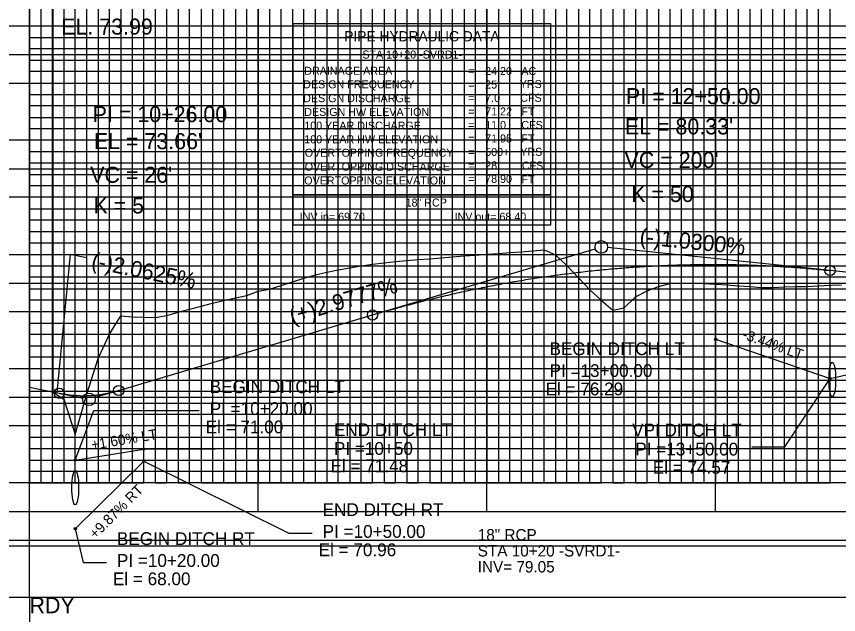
# Model space of a CAD drawing. Extents: x 2345490 to 2436403, y 465165 to 573888.
# Drawn here: x 2381761.1 to 2382120.5, y 510396.8 to 510658.5 of the extents above; entities that cross this region are included whole.
import ezdxf

# ---------------------------------------------------------------- set-up
doc = ezdxf.new("R2010")
doc.units = 0
for name, color, linetype in [('Old_Level_1', 7, 'Continuous'), ('Old_Level_18', 7, 'Continuous'), ('Old_Level_2', 7, 'Continuous'), ('Old_Level_3', 7, 'Continuous'), ('Old_Level_4', 7, 'Continuous'), ('Old_Level_41', 7, 'Continuous'), ('Old_Level_42', 7, 'Continuous'), ('Old_Level_43', 7, 'Continuous'), ('Old_Level_50', 7, 'Continuous'), ('Old_Level_51', 7, 'Continuous'), ('Old_Level_57', 7, 'Continuous'), ('Old_Level_63', 7, 'Continuous'), ('Prop Vertical Profile Grade', 7, 'Continuous')]:
    doc.layers.add(name, color=color, linetype=linetype)

msp = doc.modelspace()

# ---------------------------------------------------------------- linework, layer by layer
at = {"layer": 'Old_Level_1'}
msp.add_lwpolyline([(2381766.799, 510496.38628), (2381771.799, 510495.26652), (2381776.799, 510494.29703), (2381781.799, 510491.09236), (2381786.799, 510475.545), (2381791.799, 510493.23682), (2381796.799, 510508.82896), (2381801.799, 510519.43585), (2381806.799, 510527.46772), (2381811.799, 510527.16316), (2381816.799, 510526.92701), (2381821.799, 510526.73293), (2381826.799, 510527.68325), (2381831.799, 510529.13877), (2381836.799, 510530.47008), (2381841.799, 510531.75771), (2381846.799, 510533.00023), (2381851.799, 510534.19626), (2381856.799, 510535.34447), (2381861.799, 510536.44358), (2381866.799, 510538.26535), (2381871.799, 510539.18964), (2381876.799, 510540.85295), (2381881.799, 510542.44657), (2381886.799, 510543.96872), (2381891.799, 510545.41772), (2381896.799, 510546.68661), (2381901.799, 510547.6733), (2381906.799, 510548.57556), (2381911.799, 510549.39239), (2381916.799, 510550.12286), (2381921.799, 510550.76618), (2381926.799, 510551.32163), (2381931.799, 510551.78859), (2381936.799, 510552.17014), (2381941.799, 510552.5288), (2381946.799, 510552.88746), (2381951.799, 510553.34688), (2381956.799, 510553.71799), (2381961.799, 510554.0891), (2381966.799, 510554.46021), (2381971.799, 510554.83132), (2381976.799, 510555.20243), (2381981.799, 510555.57354), (2381986.799, 510555.94465), (2381991.799, 510556.34881), (2381996.799, 510554.23512), (2382001.799, 510549.54421), (2382006.799, 510544.21219), (2382011.799, 510538.85622), (2382016.799, 510534.42474), (2382021.799, 510529.99327), (2382026.799, 510531.06065), (2382031.799, 510535.83309), (2382036.799, 510538.39836), (2382041.799, 510540.30035), (2382046.799, 510541.74515), (2382051.799, 510541.98873), (2382056.799, 510541.81563), (2382061.799, 510541.64254), (2382066.799, 510541.39711), (2382071.799, 510541.05134), (2382076.799, 510540.72909), (2382081.799, 510540.40571), (2382086.799, 510539.94628), (2382091.799, 510539.9297), (2382096.799, 510540.14654), (2382101.799, 510540.31913), (2382106.799, 510540.43366), (2382111.799, 510540.67643), (2382116.799, 510540.9192), (2382121.799, 510541.16197)], dxfattribs=at)
at = {"layer": 'Old_Level_18'}
msp.add_lwpolyline([(2383216.79875, 511479.3835), (2381716.79875, 511479.3835), (2381716.79875, 510429.3835), (2383216.79875, 510429.3835)], close=True, dxfattribs=at)
at = {"layer": 'Old_Level_2'}
for p, q in [((2381777.109, 510494.2375), (2381777.109, 510684.44001)), ((2382116.799, 510547.3835), (2382116.799, 510681.70631)), ((2381784.50848, 510554.29431), (2381778.8217, 510494.02737)), ((2381791.76888, 510552.84223), (2381784.50848, 510554.29431)), ((2381916.799, 510527.90671), (2382014.16336, 510556.89869)), ((2382116.799, 510547.3835), (2382019.53453, 510557.40174)), ((2381779.799, 510493.66475), (2381790.10569, 510491.539)), ((2381805.799, 510494.85448), (2381795.43464, 510491.76831))]:
    msp.add_line(p, q, dxfattribs=at)
for centre, radius in [((2382016.799, 510557.6835), 2.75), ((2382116.799, 510547.3835), 2.25), ((2381916.799, 510527.90671), 2.25), ((2381805.799, 510494.85448), 2.25), ((2381779.799, 510493.66475), 2.25), ((2381792.799, 510490.9835), 2.75)]:
    msp.add_circle(centre, radius, dxfattribs=at)
at = {"layer": 'Old_Level_3'}
for p, q in [((2382066.799, 510504.39502), (2382066.799, 510517.2835)), ((2382066.799, 510517.2835), (2382116.799, 510500.0835)), ((2382116.799, 510500.0835), (2382166.799, 510511.3835)), ((2382049.36634, 510504.39502), (2382066.799, 510504.39502)), ((2382097.05969, 510470.20539), (2382116.799, 510500.0835)), ((2381786.799, 510464.3835), (2381794.9392, 510486.13954)), ((2381794.9392, 510486.13954), (2381841.03359, 510486.13954)), ((2381786.799, 510464.3835), (2381816.799, 510469.1835)), ((2381816.799, 510469.1835), (2381879.16663, 510469.46159)), ((2381879.16663, 510469.46159), (2381892.35737, 510469.46159)), ((2382082.54842, 510470.20539), (2382097.05969, 510470.20539)), ((2381786.799, 510434.3835), (2381816.799, 510463.9835)), ((2381816.799, 510463.9835), (2381880.13742, 510432.37177)), ((2381786.799, 510434.3835), (2381790.19861, 510419.66303)), ((2381880.13742, 510432.37177), (2381890.40218, 510432.37177)), ((2381790.19861, 510419.66303), (2381800.46337, 510419.66303))]:
    msp.add_line(p, q, dxfattribs=at)
for centre in [(2382066.799, 510517.2835), (2382116.799, 510500.0835), (2381816.799, 510469.1835), (2381786.799, 510464.3835), (2381816.799, 510463.9835), (2381786.799, 510434.3835)]:
    msp.add_circle(centre, 0.5, dxfattribs=at)
for centre in [(2382117.799, 510499.6835), (2381786.799, 510452.3835)]:
    msp.add_ellipse(centre, major_axis=(0, 7.5), ratio=0.195724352, dxfattribs=at)
at = {"layer": 'Old_Level_4'}
for p, q in [((2381882.02849, 510655.45163), (2381994.52849, 510655.45163)), ((2381882.02849, 510580.45163), (2381882.02849, 510655.45163)), ((2381994.52849, 510655.45163), (2381994.52849, 510580.45163)), ((2381994.52849, 510580.45163), (2381882.02849, 510580.45163))]:
    msp.add_line(p, q, dxfattribs=at)
msp.add_lwpolyline([(2381882.02849, 510580.45163), (2381994.52849, 510580.45163), (2381994.52849, 510567.23663), (2381882.02849, 510567.23663)], close=True, dxfattribs=at)
at = {"layer": 'Old_Level_41'}
msp.add_line((2383216.79875, 510454.3835), (2381716.79875, 510454.3835), dxfattribs=at)
for points in [[(2381766.79875, 511479.3835), (2381766.79875, 510454.3835), (2381816.79875, 510454.3835), (2381816.79875, 511479.3835)], [(2381791.79875, 510454.3835), (2381791.79875, 511479.3835)], [(2381841.79875, 511479.3835), (2381841.79875, 510454.3835), (2381891.79875, 510454.3835), (2381891.79875, 511479.3835)], [(2381866.79875, 511479.3835), (2381866.79875, 510454.3835), (2381916.79875, 510454.3835), (2381916.79875, 511479.3835)], [(2381941.79875, 511479.3835), (2381941.79875, 510454.3835), (2381991.79875, 510454.3835), (2381991.79875, 511479.3835)], [(2381966.79875, 511479.3835), (2381966.79875, 510454.3835), (2382016.79875, 510454.3835), (2382016.79875, 511479.3835)], [(2382041.79875, 511479.3835), (2382041.79875, 510454.3835), (2382091.79875, 510454.3835), (2382091.79875, 511479.3835)], [(2382066.79875, 511479.3835), (2382066.79875, 510454.3835), (2382116.79875, 510454.3835), (2382116.79875, 511479.3835)], [(2383216.79875, 510679.3835), (2381716.79875, 510679.3835), (2381716.79875, 510629.3835), (2383216.79875, 510629.3835)], [(2383216.79875, 510579.3835), (2381716.79875, 510579.3835), (2381716.79875, 510529.3835), (2383216.79875, 510529.3835)], [(2383216.79875, 510504.3835), (2381716.79875, 510504.3835), (2381716.79875, 510554.3835), (2383216.79875, 510554.3835)], [(2383216.79875, 510479.3835), (2381716.79875, 510479.3835)]]:
    msp.add_lwpolyline(points, dxfattribs=at)
at = {"layer": 'Old_Level_42'}
msp.add_lwpolyline([(2383216.79875, 510604.3835), (2381716.79875, 510604.3835), (2381716.79875, 510654.3835), (2383216.79875, 510654.3835)], dxfattribs=at)
at = {"layer": 'Old_Level_43'}
for points in [[(2381771.79875, 511479.3835), (2381771.79875, 510454.3835), (2381776.79875, 510454.3835), (2381776.79875, 511479.3835)], [(2381781.79875, 511479.3835), (2381781.79875, 510454.3835), (2381786.79875, 510454.3835), (2381786.79875, 511479.3835)], [(2381796.79875, 511479.3835), (2381796.79875, 510454.3835), (2381801.79875, 510454.3835), (2381801.79875, 511479.3835)], [(2381806.79875, 511479.3835), (2381806.79875, 510454.3835), (2381811.79875, 510454.3835), (2381811.79875, 511479.3835)], [(2381821.79875, 511479.3835), (2381821.79875, 510454.3835), (2381826.79875, 510454.3835), (2381826.79875, 511479.3835)], [(2381831.79875, 511479.3835), (2381831.79875, 510454.3835), (2381836.79875, 510454.3835), (2381836.79875, 511479.3835)], [(2381846.79875, 511479.3835), (2381846.79875, 510454.3835), (2381851.79875, 510454.3835), (2381851.79875, 511479.3835)], [(2381856.79875, 511479.3835), (2381856.79875, 510454.3835), (2381861.79875, 510454.3835), (2381861.79875, 511479.3835)], [(2381871.79875, 511479.3835), (2381871.79875, 510454.3835), (2381876.79875, 510454.3835), (2381876.79875, 511479.3835)], [(2381881.79875, 511479.3835), (2381881.79875, 510454.3835), (2381886.79875, 510454.3835), (2381886.79875, 511479.3835)], [(2381896.79875, 511479.3835), (2381896.79875, 510454.3835), (2381901.79875, 510454.3835), (2381901.79875, 511479.3835)], [(2381906.79875, 511479.3835), (2381906.79875, 510454.3835), (2381911.79875, 510454.3835), (2381911.79875, 511479.3835)], [(2381921.79875, 511479.3835), (2381921.79875, 510454.3835), (2381926.79875, 510454.3835), (2381926.79875, 511479.3835)], [(2381931.79875, 510454.3835), (2381936.79875, 510454.3835), (2381936.79875, 511479.3835)], [(2381931.79875, 511479.3835), (2381931.79875, 510454.3835)], [(2381946.79875, 511479.3835), (2381946.79875, 510454.3835), (2381951.79875, 510454.3835), (2381951.79875, 511479.3835)], [(2381956.79875, 511479.3835), (2381956.79875, 510454.3835), (2381961.79875, 510454.3835), (2381961.79875, 511479.3835)], [(2381971.79875, 511479.3835), (2381971.79875, 510454.3835), (2381976.79875, 510454.3835), (2381976.79875, 511479.3835)], [(2381981.79875, 511479.3835), (2381981.79875, 510454.3835), (2381986.79875, 510454.3835), (2381986.79875, 511479.3835)], [(2381996.79875, 511479.3835), (2381996.79875, 510454.3835), (2382001.79875, 510454.3835), (2382001.79875, 511479.3835)], [(2382006.79875, 511479.3835), (2382006.79875, 510454.3835), (2382011.79875, 510454.3835), (2382011.79875, 511479.3835)], [(2382021.79875, 511479.3835), (2382021.79875, 510454.3835), (2382026.79875, 510454.3835), (2382026.79875, 511479.3835)], [(2382031.79875, 511479.3835), (2382031.79875, 510454.3835), (2382036.79875, 510454.3835), (2382036.79875, 511479.3835)], [(2382046.79875, 511479.3835), (2382046.79875, 510454.3835), (2382051.79875, 510454.3835), (2382051.79875, 511479.3835)], [(2382056.79875, 511479.3835), (2382056.79875, 510454.3835), (2382061.79875, 510454.3835), (2382061.79875, 511479.3835)], [(2382071.79875, 511479.3835), (2382071.79875, 510454.3835), (2382076.79875, 510454.3835), (2382076.79875, 511479.3835)], [(2382081.79875, 511479.3835), (2382081.79875, 510454.3835), (2382086.79875, 510454.3835), (2382086.79875, 511479.3835)], [(2382096.79875, 511479.3835), (2382096.79875, 510454.3835), (2382111.79875, 510454.3835), (2382111.79875, 511479.3835)], [(2382101.79875, 511479.3835), (2382101.79875, 510454.3835), (2382106.79875, 510454.3835), (2382106.79875, 511479.3835)], [(2382101.79875, 511478.7835), (2382101.79875, 510454.3835), (2382106.79875, 510454.3835), (2382106.79875, 511478.7835)], [(2381766.79875, 510649.3835), (2383166.79875, 510649.3835)], [(2383166.79875, 510644.3835), (2381766.79875, 510644.3835), (2381766.79875, 510639.3835), (2383166.79875, 510639.3835)], [(2383166.79875, 510634.3835), (2381766.79875, 510634.3835)], [(2381766.79875, 510624.3835), (2383166.79875, 510624.3835)], [(2383166.79875, 510619.3835), (2381766.79875, 510619.3835), (2381766.79875, 510614.3835), (2383166.79875, 510614.3835)], [(2383166.79875, 510609.3835), (2381766.79875, 510609.3835), (2381766.79875, 510599.3835), (2383166.79875, 510599.3835)], [(2383166.79875, 510594.3835), (2381766.79875, 510594.3835), (2381766.79875, 510589.3835), (2383166.79875, 510589.3835)], [(2383166.79875, 510584.3835), (2381766.79875, 510584.3835), (2381766.79875, 510574.3835), (2383166.79875, 510574.3835)], [(2383166.79875, 510569.3835), (2381766.79875, 510569.3835), (2381766.79875, 510564.3835), (2383166.79875, 510564.3835)], [(2383166.79875, 510559.3835), (2381766.79875, 510559.3835), (2381766.79875, 510549.3835), (2383166.79875, 510549.3835)], [(2383166.79875, 510544.3835), (2381766.79875, 510544.3835), (2381766.79875, 510539.3835), (2383166.79875, 510539.3835)], [(2383166.79875, 510534.3835), (2381766.79875, 510534.3835), (2381766.79875, 510524.3835), (2383166.79875, 510524.3835)], [(2383166.79875, 510519.3835), (2381766.79875, 510519.3835), (2381766.79875, 510514.3835), (2383166.79875, 510514.3835)], [(2383166.79875, 510509.3835), (2381766.79875, 510509.3835), (2381766.79875, 510499.3835), (2383166.79875, 510499.3835)], [(2383166.79875, 510494.3835), (2381766.79875, 510494.3835), (2381766.79875, 510489.3835), (2383166.79875, 510489.3835)], [(2383166.79875, 510484.3835), (2381766.79875, 510484.3835), (2381766.79875, 510474.3835), (2383166.79875, 510474.3835)], [(2383166.79875, 510469.3835), (2381766.79875, 510469.3835), (2381766.79875, 510464.3835), (2383166.79875, 510464.3835)], [(2383166.79875, 510459.3835), (2381766.79875, 510459.3835)]]:
    msp.add_lwpolyline(points, dxfattribs=at)
at = {"layer": 'Old_Level_50'}
msp.add_lwpolyline([(2383229.29875, 511481.9335), (2381562.79875, 511481.9335), (2381562.79875, 510426.8335), (2383229.29875, 510426.8335)], close=True, dxfattribs=at)
at = {"layer": 'Old_Level_51'}
msp.add_lwpolyline([(2383233.79875, 511504.3835), (2381549.79875, 511504.3835), (2381549.79875, 510404.3835), (2383233.79875, 510404.3835)], close=True, dxfattribs=at)
at = {"layer": 'Old_Level_57'}
for p, q in [((2381766.79875, 510441.88375), (2381766.79875, 510691.88375)), ((2381866.79875, 510441.88375), (2381866.79875, 510691.88375)), ((2381966.79875, 510441.88375), (2381966.79875, 510691.88375)), ((2382066.79875, 510441.88375), (2382066.79875, 510691.88375)), ((2381716.79925, 510641.88375), (2383066.79875, 510641.88375)), ((2381716.79925, 510591.88375), (2383066.79875, 510591.88375)), ((2381716.79925, 510541.88375), (2383066.79875, 510541.88375)), ((2381716.799, 510491.88375), (2383066.79875, 510491.88375)), ((2381716.79925, 510441.88375), (2383066.79875, 510441.88375))]:
    msp.add_line(p, q, dxfattribs=at)
at = {"layer": 'Old_Level_63'}
for q in [(2381766.799, 512904.3835), (2382366.799, 510404.3835), (2381766.799, 507904.3835)]:
    msp.add_line((2381766.799, 510404.3835), q, dxfattribs=at)
at = {"layer": 'Prop Vertical Profile Grade'}
for p, q in [((2382166.799, 510542.02672), (2382116.799, 510547.3835)), ((2381805.799, 510494.85448), (2381916.799, 510527.90671)), ((2381776.799, 510494.2835), (2381779.799, 510493.66475))]:
    msp.add_line(p, q, dxfattribs=at)
for points in [[(2381916.799, 510527.90671), (2381920.799, 510529.08175), (2381924.799, 510530.22473), (2381928.799, 510531.33565), (2381932.799, 510532.41451), (2381936.799, 510533.4613), (2381940.799, 510534.47604), (2381944.799, 510535.45871), (2381948.799, 510536.40932), (2381952.799, 510537.32787), (2381956.799, 510538.21436), (2381960.799, 510539.06878), (2381964.799, 510539.89115), (2381968.799, 510540.68145), (2381972.799, 510541.43969), (2381976.799, 510542.16588), (2381980.799, 510542.85999), (2381984.799, 510543.52205), (2381988.799, 510544.15205), (2381992.799, 510544.74998), (2381996.799, 510545.31586), (2382000.799, 510545.84967), (2382004.799, 510546.35142), (2382008.799, 510546.82111), (2382012.799, 510547.25874), (2382016.799, 510547.6643), (2382020.799, 510548.03781), (2382024.799, 510548.37925), (2382028.799, 510548.68863), (2382032.799, 510548.96596), (2382036.799, 510549.21121), (2382040.799, 510549.42441), (2382044.799, 510549.60555), (2382048.799, 510549.75462), (2382052.799, 510549.87164), (2382056.799, 510549.95659), (2382060.799, 510550.00948), (2382064.799, 510550.03031), (2382068.799, 510550.01908), (2382072.799, 510549.97578), (2382076.799, 510549.90043), (2382080.799, 510549.79301), (2382084.799, 510549.65353), (2382088.799, 510549.482), (2382092.799, 510549.27839), (2382096.799, 510549.04273), (2382100.799, 510548.77501), (2382104.799, 510548.47522), (2382108.799, 510548.14338), (2382112.799, 510547.77947), (2382116.799, 510547.3835)], [(2381779.799, 510493.66475), (2381780.319, 510493.56012), (2381780.839, 510493.46073), (2381781.359, 510493.36659), (2381781.879, 510493.27768), (2381782.399, 510493.19402), (2381782.919, 510493.1156), (2381783.439, 510493.04242), (2381783.959, 510492.97449), (2381784.479, 510492.91179), (2381784.999, 510492.85434), (2381785.519, 510492.80213), (2381786.039, 510492.75516), (2381786.559, 510492.71343), (2381787.079, 510492.67695), (2381787.599, 510492.6457), (2381788.119, 510492.6197), (2381788.639, 510492.59894), (2381789.159, 510492.58342), (2381789.679, 510492.57314), (2381790.199, 510492.56811), (2381790.719, 510492.56831), (2381791.239, 510492.57376), (2381791.759, 510492.58445), (2381792.279, 510492.60038), (2381792.799, 510492.62156), (2381793.319, 510492.64797), (2381793.839, 510492.67963), (2381794.359, 510492.71653), (2381794.879, 510492.75867), (2381795.399, 510492.80605), (2381795.919, 510492.85868), (2381796.439, 510492.91654), (2381796.959, 510492.97965), (2381797.479, 510493.048), (2381797.999, 510493.12159), (2381798.519, 510493.20043), (2381799.039, 510493.2845), (2381799.559, 510493.37382), (2381800.079, 510493.46838), (2381800.599, 510493.56818), (2381801.119, 510493.67322), (2381801.639, 510493.7835), (2381802.159, 510493.89903), (2381802.679, 510494.0198), (2381803.199, 510494.14581), (2381803.719, 510494.27706), (2381804.239, 510494.41355), (2381804.759, 510494.55529), (2381805.279, 510494.70226), (2381805.799, 510494.85448)]]:
    msp.add_spline(points, degree=3, dxfattribs=at)

# ---------------------------------------------------------------- texts
at = {"layer": 'Old_Level_2'}
for s, height, p in [('EL. 73.99', 7.000001, (2381780.66053, 510650.59203)), ('PI = 12+50.00', 7, (2382027.60025, 510620.1666)), ('PI = 10+26.00', 7, (2381794.42908, 510612.27802)), ("EL = 80.33'", 7, (2382027.11891, 510606.90534)), ("EL = 73.66'", 7, (2381794.91042, 510600.46076)), ("VC = 200'", 7, (2382026.98125, 510592.22043)), ("VC = 26'", 7, (2381793.32874, 510585.75548)), ('K = 50', 7, (2382029.86927, 510577.34015)), ('K = 5', 7, (2381794.77276, 510572.31922))]:
    msp.add_text(s, height=height, dxfattribs=at).set_placement(p)
for s, rotation, p in [('(-)1.0300%', 354.1192724, (2382033.32422, 510558.99727)), ('(-)2.0625%', 348.3461594, (2381793.46367, 510548.57707)), ('(+)2.9777%', 16.5818398, (2381881.68354, 510523.93216))]:
    msp.add_text(s, height=7, rotation=rotation, dxfattribs=at).set_placement(p)
at = {"layer": 'Old_Level_3'}
for s, height, rotation, p in [('-3.44% LT', 4.48, 340.1418463, (2382078.11388, 510517.66527)), ('BEGIN DITCH LT', 5.6000004, 360, (2381994.18539, 510510.32954)), ('PI =13+00.00', 5.6000004, 360, (2381994.18539, 510500.76575)), ('BEGIN DITCH LT', 5.6000004, 360, (2381845.59083, 510493.71041)), ('El = 76.29', 5.6, 360, (2381992.42877, 510492.74647)), ('PI =10+20.00', 5.6000004, 360, (2381845.59083, 510484.14662)), ('El = 71.00', 5.6, 360, (2381843.83422, 510476.12734)), ('END DITCH LT', 5.6000004, 360, (2381899.88883, 510474.88935)), ('VPI DITCH LT', 5.6000004, 360, (2382030.29962, 510474.76123)), ('+1.60% LT', 4.48, 9.4623222, (2381794.14851, 510468.85455)), ('PI =10+50', 5.6, 360, (2381899.88883, 510466.69466)), ('PI =13+50.00', 5.6000004, 360, (2382031.66968, 510466.42017)), ('El = 71.48', 5.6, 360, (2381898.42499, 510459.06574)), ('El = 74.57', 5.6, 360, (2382039.30832, 510458.39708)), ('+9.87% RT', 4.48, 44.9999778, (2381795.62558, 510429.66969)), ('END DITCH RT', 5.6000004, 360, (2381894.95942, 510439.94264)), ('PI =10+50.00', 5.6000004, 360, (2381894.95942, 510430.37886)), ('BEGIN DITCH RT', 5.6000004, 360, (2381805.02061, 510427.2339)), ('El = 70.96', 5.6, 360, (2381893.2028, 510422.35957)), ('PI =10+20.00', 5.6000004, 360, (2381805.02061, 510417.67011)), ('El = 68.00', 5.6, 360, (2381803.26399, 510409.65083))]:
    msp.add_text(s, height=height, rotation=rotation, dxfattribs=at).set_placement(p)
for s, height, p in [('18" RCP', 4.999999, (2381962.7762, 510429.22611)), ('STA 10+20 -SVRD1-', 4.9999995, (2381962.7762, 510422.22611)), ('INV= 79.05', 4.999999, (2381962.7762, 510415.22611))]:
    msp.add_text(s, height=height, dxfattribs=at).set_placement(p)
at = {"layer": 'Old_Level_4'}
for s, height, p in [('PIPE HYDRAULIC DATA', 4.49985, (2381904.42849, 510647.62663)), ('STA 10+20 -SVRD1-', 3.4998, (2381912.32224, 510640.12638)), ('DRAINAGE AREA', 3.49995, (2381886.92849, 510633.00163)), ('=        ', 3.49995, (2381958.57849, 510632.90163)), ('24.20', 3.49995, (2381966.03899, 510632.90118)), ('AC', 3.49995, (2381981.85349, 510632.90163)), ('DESIGN FREQUENCY', 3.49995, (2381886.47849, 510627.07663)), ('25', 3.49995, (2381966.03899, 510627.00123)), ('YRS', 3.49995, (2381981.15349, 510627.20163)), ('=        ', 3.49995, (2381958.57849, 510627.00163)), ('DESIGN DISCHARGE', 3.49995, (2381886.47849, 510621.00163)), ('=        ', 3.49995, (2381958.57849, 510621.10163)), ('7.0', 3.49995, (2381966.03899, 510621.10128)), ('CFS', 3.49995, (2381981.37849, 510621.17663)), ('DESIGN HW ELEVATION', 3.49995, (2381886.92849, 510615.00163)), ('=        ', 3.49995, (2381958.57849, 510615.20163)), ('71.22', 3.49995, (2381966.03899, 510615.20133)), ('FT', 3.49995, (2381981.85349, 510615.20163)), ('100 YEAR DISCHARGE', 3.49995, (2381886.92849, 510609.00163)), ('=        ', 3.49995, (2381958.57849, 510609.30163)), ('11.0', 3.49995, (2381966.03899, 510609.30138)), ('CFS', 3.49995, (2381981.85349, 510609.30163)), ('100 YEAR HW ELEVATION', 3.49995, (2381886.92849, 510603.00163)), ('=        ', 3.49995, (2381958.57849, 510603.40163)), ('71.95', 3.49995, (2381966.03899, 510603.40143)), ('FT', 3.49995, (2381981.85349, 510603.40163)), ('500+', 3.49995, (2381966.03899, 510597.50148)), ('YRS', 3.49995, (2381981.37849, 510597.55163)), ('OVERTOPPING FREQUENCY', 3.49995, (2381887.15349, 510597.15163)), ('=        ', 3.49995, (2381958.57849, 510597.50163)), ('OVERTOPPING DISCHARGE', 3.49995, (2381887.15349, 510591.02663)), ('=        ', 3.49995, (2381958.57849, 510591.60163)), ('28', 3.49995, (2381966.03899, 510591.60153)), ('CFS', 3.49995, (2381982.07849, 510591.52663)), ('OVERTOPPING ELEVATION', 3.49995, (2381886.92849, 510585.00163)), ('=        ', 3.49995, (2381958.57849, 510585.70163)), ('78.90', 3.49995, (2381966.03899, 510585.70158)), ('FT', 3.49995, (2381981.85349, 510585.50163)), ('18" RCP', 3.4998, (2381931.23424, 510575.34938)), ('INV in= 69.70', 3.4998, (2381884.96099, 510569.16363)), ('INV out= 68.40', 3.4998, (2381952.63774, 510569.16363))]:
    msp.add_text(s, height=height, dxfattribs=at).set_placement(p)
at = {"layer": 'Old_Level_63'}
msp.add_text('RDY', height=7.000001, dxfattribs=at).set_placement((2381766.799, 510397.3835))

doc.saveas('drawing.dxf')
